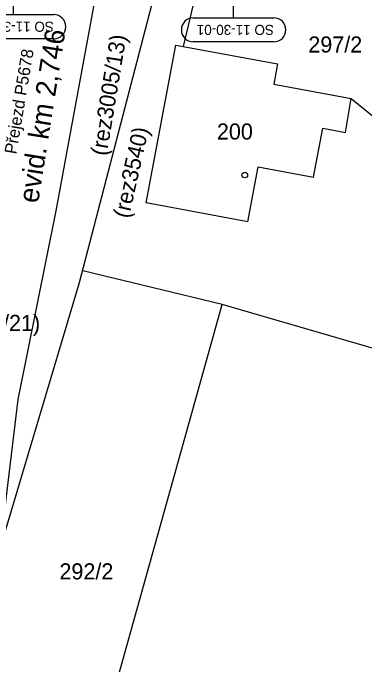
# Model space of a CAD drawing. Extents: x -728800 to -728100, y -1073200 to -1072700.
# Drawn here: x -728508.97 to -728487.13, y -1073097.26 to -1073056.8 of the extents above; entities that cross this region are included whole.
import ezdxf

# ---------------------------------------------------------------- set-up
doc = ezdxf.new("R2010")
doc.units = 0
for name, color, linetype in [('B6_JŽM', 7, 'Continuous'), ('K_01_Hranice parcel', 7, 'Continuous'), ('K_02_Parcelní čísla', 7, 'Continuous'), ('K_03_Značky druhu pozemku', 7, 'Continuous'), ('K_04_Vnitřní kresba', 7, 'Continuous'), ('K_05_Značky stavební objekty', 7, 'Continuous'), ('KTA_členění PS a SO', 7, 'Continuous')]:
    doc.layers.add(name, color=color, linetype=linetype)

msp = doc.modelspace()

# ---------------------------------------------------------------- linework, layer by layer
at = {"layer": 'K_01_Hranice parcel'}
for p, q in [((-728496.81, -1073052.21), (-728498.42, -1073058.87)), ((-728499.33, -1073052.26), (-728504.87, -1073073.55)), ((-728494.393, -1073069.768), (-728500.7, -1073068.59))]:
    msp.add_line(p, q, dxfattribs=at)
for points in [[(-728503.24, -1073052.34), (-728506.32, -1073069.08), (-728508.676, -1073080.788), (-728509.816, -1073090.065)], [(-728500.7, -1073068.59), (-728498.87, -1073058.79), (-728498.42, -1073058.87), (-728492.55, -1073059.96), (-728492.79, -1073061.21), (-728487.98, -1073062.11), (-728486.26, -1073063.51), (-728481.72, -1073063.46)], [(-728476.28, -1073080.622), (-728495.997, -1073074.887), (-728504.645, -1073072.797)], [(-728504.87, -1073073.55), (-728509.816, -1073090.065), (-728516.822, -1073108.739), (-728518.032, -1073119.517), (-728508.074, -1073118.154), (-728495.997, -1073074.887)]]:
    msp.add_lwpolyline(points, dxfattribs=at)
at = {"layer": 'K_03_Značky druhu pozemku'}
msp.add_circle((-728494.588, -1073066.858), 0.175, dxfattribs=at)
at = {"layer": 'K_04_Vnitřní kresba'}
msp.add_lwpolyline([(-728494.393, -1073069.768), (-728493.75, -1073066.34), (-728490.32, -1073066.98), (-728489.74, -1073063.94), (-728488.34, -1073064.21), (-728487.98, -1073062.11)], dxfattribs=at)
at = {"layer": 'K_05_Značky stavební objekty'}
msp.add_circle((-728494.588, -1073066.858), 0.175, dxfattribs=at)
at = {"layer": 'KTA_členění PS a SO'}
for p, q in [((-728508.938, -1073056.9), (-728508.938, -1073054.9)), ((-728495.283, -1073057.094), (-728495.283, -1073055.094))]:
    msp.add_line(p, q, dxfattribs=at)
for points in [[(-728511.438, -1073056.9), (-728506.438, -1073056.9)], [(-728497.783, -1073057.094), (-728492.783, -1073057.094)], [(-728506.438, -1073058.4), (-728511.438, -1073058.4)], [(-728492.783, -1073058.594), (-728497.783, -1073058.594)]]:
    msp.add_lwpolyline(points, dxfattribs=at)
for centre, start, end in [((-728506.444, -1073057.65), 270.4529, 89.5471), ((-728497.777, -1073057.844), 90.4529, 269.5471), ((-728492.789, -1073057.844), 270.4529, 89.5471)]:
    msp.add_arc(centre, 0.75, start, end, dxfattribs=at)

# ---------------------------------------------------------------- texts
at = {"layer": 'B6_JŽM'}
for s, height, rotation, p in [('evid. km 2,746', 1.25, 80.9732, (-728507.415, -1073068.648)), ('Přejezd P5678', 0.75, 80.4567, (-728508.77, -1073065.594))]:
    msp.add_text(s, height=height, rotation=rotation, dxfattribs=at).set_placement(p)
at = {"layer": 'K_02_Parcelní čísla'}
for s, rotation, p in [('(rez3005/13)', 80.5728, (-728503.171, -1073065.701)), ('(rez3540)', 77.3647, (-728501.791, -1073069.585))]:
    msp.add_text(s, height=1, rotation=rotation, dxfattribs=at).set_placement(p)
for s, p in [('297/2', (-728490.649, -1073059.255)), ('200', (-728496.32, -1073064.655)), ('(rez3005/21)', (-728514.867, -1073076.536)), ('292/2', (-728506.091, -1073091.955))]:
    msp.add_text(s, height=1, dxfattribs=at).set_placement(p)
at = {"layer": 'KTA_členění PS a SO'}
for p in [(-728506.439, -1073057.341), (-728492.784, -1073057.536)]:
    msp.add_text('SO 11-30-01', height=0.625, rotation=180, dxfattribs=at).set_placement(p)

doc.saveas('drawing.dxf')
